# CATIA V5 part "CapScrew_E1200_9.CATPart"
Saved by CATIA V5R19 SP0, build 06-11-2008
Part number: CapScrew_E1200_9
Nomenclature: E 1200/5x12
Source: Unknown
Description: MEUSBURGER
Bounding box of the stored display mesh (mm): x -4.249 to 4.25, y -4.25 to 4.245, z 0 to 17
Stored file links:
  C:\Users\jsmid\Desktop\DP_Smidak_Forma LEGO\CapScrew_E1200_9.CATPart
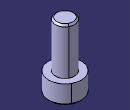
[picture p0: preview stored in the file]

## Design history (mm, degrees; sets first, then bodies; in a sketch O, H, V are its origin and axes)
Body1 (main body)
  Solid1 "PartBody": solid without history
